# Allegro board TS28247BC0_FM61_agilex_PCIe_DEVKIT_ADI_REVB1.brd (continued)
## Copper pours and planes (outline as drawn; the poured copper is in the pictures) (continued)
SI5341_1P8V_VDDO on BOTTOM: 53.6,21.41 52.97,21.41 52.84,21.54 52.84,22.68 54.36,22.68 54.74,22.3 54.74,20.78 54.62,20.65 53.86,20.65 53.73,20.78 53.73,21.29
SI5341_1P8V_VDDO on L12_SIG4: 54.74,30.69 54.36,31.07 48.27,31.07 47.89,30.69 47.89,20.53 48.27,20.14 54.36,20.14 54.74,20.53
SI5341_2P5V_VDDO on BOTTOM: 47,21.29 47,22.56 47.12,22.68 48.01,22.68 48.14,22.56 48.14,21.41 48.01,21.29
SI5341_2P5V_VDDO on L03_SIG1: 52.84,24.34 51.44,22.94 51.44,22.05 51.19,21.8 46.62,21.8 46.24,22.18 46.24,26.24 46.62,26.62 52.46,26.62 52.84,26.24
SI5341_VDD on BOTTOM: 47.51,29.29 47.63,29.42 47.63,31.45 47.51,31.57 46.11,31.57 45.98,31.45 45.98,29.29
SI5341_VDD on L03_SIG1: 49.54,31.83 50.43,30.94 54.49,30.94 55.13,30.3 55.13,22.3 54.62,21.8 52.08,21.8 51.82,22.05 51.82,22.68 53.22,24.08 53.22,26.49 52.71,27 46.62,27 46.24,27.38 46.24,31.45 46.62,31.83
SI5341_VDDA on BOTTOM: 44.58,22.81 44.58,24.34 43.57,24.34 43.31,24.08 43.31,23.07 43.57,22.81
SW_U76_FPGA_VCC on TOP: 184.74,87.25 184.74,84.3 184.64,84.2 183.12,84.2 182.81,83.89 182.81,82.88 183.14,82.55 184.67,82.55 184.74,82.47 184.74,79.55 184.31,79.12 178.09,79.12 177.46,79.75 177.46,87.14 178,87.68 184.31,87.68
SW_U77_FPGA_VCC on TOP: 184.74,74.6 184.74,71.66 184.64,71.55 183.12,71.55 182.81,71.25 182.81,70.23 183.14,69.9 184.67,69.9 184.74,69.83 184.74,67.08 184.13,66.47 178.14,66.47 177.48,67.13 177.48,72.91 178.33,73.76 179.51,73.76 180.78,75.03 184.31,75.03
SW_U77_FPGA_VCC on BOTTOM, L07_SIG3, L16_SIG6: 184.74,74.6 184.74,67.08 184.13,66.47 181.06,66.47 179.13,68.4 179.13,73.38 180.78,75.03 184.31,75.03
SW_U78_FPGA_VCC on TOP: 184.74,59.06 184.74,56.11 184.72,56.09 183.19,56.09 182.81,55.7 182.81,54.69 183.14,54.36 184.67,54.36 184.74,54.28 184.74,51.36 184.31,50.93 178.29,50.93 177.49,51.73 177.49,58.61 178.37,59.49 184.31,59.49
SW_U78_FPGA_VCC on BOTTOM, L16_SIG6: 184.74,59.06 184.74,51.36 184.31,50.93 181.06,50.93 179.13,52.86 179.13,57.48 181.13,59.49 184.31,59.49
SW_U78_FPGA_VCC on L07_SIG3: 184.74,59.06 184.74,56.67 183.67,55.6 183.67,54.61 184.74,53.55 184.74,51.36 184.31,50.93 181.06,50.93 179.13,52.86 179.13,57.48 181.13,59.49 184.31,59.49
SW_U79_FPGA_VCC on TOP: 184.74,42.88 184.74,39.93 184.64,39.83 183.12,39.83 182.81,39.53 182.81,38.51 183.14,38.18 184.67,38.18 184.74,38.1 184.74,35.18 184.31,34.75 177.91,34.75 177.49,35.17 177.49,43.02 177.78,43.31 184.31,43.31
SW_U79_FPGA_VCC on BOTTOM, L16_SIG6: 184.74,42.88 184.74,35.18 184.31,34.75 181.06,34.75 179.13,36.68 179.13,41.3 181.13,43.31 184.31,43.31
UART_USB_PGND on BOTTOM: 19.59,106.35 19.59,107.04 20.58,108.03 20.58,108.79 15.25,108.79 15.25,108.03 16.26,107.01 16.26,106.38 15.37,105.49 15.37,104.98 15.25,104.85 13.85,104.85 13.85,106.89 13.34,107.39 13.34,110.44 22.49,110.44 22.49,107.9 20.66,106.07 19.87,106.07
UBII_M10_VCCA on BOTTOM: 25.28,28.15 24.01,28.15 23.76,27.89 23.76,26.11 24.01,25.86 25.28,25.86 25.53,26.11 25.53,27.89
UBII_M10_VCCA on L09_PWR1: 39.89,14.18 39.89,31.57 22.11,31.57 22.11,14.18
USB_UART_5V on L07_SIG3: 14.74,74.25 14.74,98.76 26.17,98.76 26.17,109.81 1.28,109.81 1.28,68.4 1.91,67.77 26.93,67.77 27.31,68.15 27.31,73.87 26.93,74.25
N17328275 on BOTTOM: 64.27,92.03 64.52,91.77 66.56,91.77 66.81,92.03 66.81,96.73 66.56,96.98 64.52,96.98 64.27,96.73
N31257069 on TOP: 54.36,5.79 53.98,6.17 53.98,8.46 54.24,8.71 54.87,8.71 55.13,8.46 55.13,5.92 55,5.79 55,3.38 54.87,3.25 54.49,3.25 54.36,3.38
N31257069 on BOTTOM: 54.24,7.19 54.87,7.19 55.13,7.44 55.13,10.75 55,10.87 54.49,10.87 54.49,9.6 53.98,9.1 53.98,7.44
N31416063 on BOTTOM: 244.36,83.37 244.61,83.11 246.34,83.11 246.36,83.14 246.36,85.04 246.29,85.12 244.58,85.12 244.36,84.89
N34525726 on TOP (solid shape): 268.87,110.13 272.25,108.91 273.3,105.48 273.3,17.17 273.1,15.32 272.09,13.75 143.17,13.75 143.17,14.43 167.7,14.43 167.7,15.83 169.23,17.36 170.77,15.83 170.77,14.43 190.56,14.43 190.56,15.8 192.08,17.34 193.63,15.83 193.63,14.43 211.51,14.43 211.51,15.75 213.05,17.29 214.59,15.75 214.59,14.43 246.44,14.43 246.44,15.75 247.99,17.28 249.49,15.7 249.49,14.43 265.38,14.43 265.67,14.59 265.69,14.93 266.97,19.91 272.1,19.55 272.42,19.5 272.6,19.78 272.6,102.68 272.34,103.08 271.86,103.02 266.53,103.28 266.18,108.61 266.22,109.15 265.77,109.43 249.51,109.43 249.51,108.08 247.97,106.54 246.44,108.08 246.44,109.43 215.5,109.43 215.5,108.11 213.98,106.54 212.43,108.08 212.43,109.43 194.9,109.43 194.9,108.11 193.36,106.57 191.83,108.11 191.83,109.43 130.13,109.43 130.13,108.11 128.61,106.54 127.06,108.08 127.06,109.43 101.18,109.43 101.18,108.11 99.65,106.54 98.1,108.08 98.1,109.43 72.35,109.43 72.35,108.11 70.82,106.54 69.27,108.08 69.27,109.43 37.88,109.43 37.88,108.11 36.35,106.54 34.81,108.08 34.81,109.43 24.14,109.43 24.14,110.13
N34525726 on BOTTOM (solid shape): 268.87,110.13 272.25,108.91 273.3,105.48 273.3,17.17 273.1,15.32 272.09,13.75 143.17,13.75 143.17,14.43 167.7,14.43 167.7,15.85 169.25,17.39 170.77,15.83 170.77,14.43 190.56,14.43 190.56,15.8 192.09,17.34 193.63,15.8 193.63,14.43 211.51,14.43 211.51,15.75 213.05,17.29 214.59,15.75 214.59,14.43 246.44,14.43 246.44,15.75 247.99,17.28 249.49,15.7 249.49,14.43 265.38,14.43 265.67,14.59 265.69,14.93 266.97,19.91 272.1,19.55 272.42,19.5 272.6,19.78 272.6,102.68 272.34,103.08 271.86,103.02 268.08,102.33 265.46,105.13 262.26,105.13 262.26,109.43 249.51,109.43 249.51,108.08 247.97,106.54 246.44,108.08 246.44,109.43 246.39,109.43 215.5,109.43 215.5,108.11 213.96,106.57 212.43,108.11 212.43,109.43 194.9,109.43 194.9,108.11 193.36,106.57 191.83,108.11 191.83,109.43 130.13,109.43 130.13,108.11 128.59,106.57 127.06,108.11 127.06,109.43 101.18,109.43 101.18,108.11 99.65,106.54 98.1,108.08 98.1,109.43 72.35,109.43 72.35,108.11 70.82,106.54 69.27,108.08 69.27,109.43 37.88,109.43 37.88,108.11 36.35,106.54 34.81,108.08 34.81,109.43 24.14,109.43 24.14,110.13
N34824147 on TOP (solid shape): 1.12,14.43 14.39,14.43 18.66,14.43 18.85,14.55 18.82,14.77 19.99,17.29 21.2,14.79 21.18,14.55 21.38,14.43 33.99,14.43 39.55,14.43 39.55,15.8 41.09,17.34 42.63,15.8 42.63,14.43 44.97,14.43 44.97,13.75 11.44,13.75 11.44,10.33 7.5,5.29 3.56,10.33 3.56,13.75 0.64,13.75 0.64,17.73 1.12,17.73
N34824147 on BOTTOM (solid shape): 1.12,14.43 14.39,14.43 18.47,14.43 18.47,15.8 20.01,17.34 21.55,15.8 21.55,14.43 33.99,14.43 39.55,14.43 39.55,15.8 41.09,17.34 42.63,15.8 42.63,14.43 44.97,14.43 44.97,13.75 11.44,13.75 11.44,10.33 7.5,5.29 3.56,10.33 3.56,13.75 0.64,13.75 0.64,17.73 1.12,17.73
N35351327 on TOP: 192.54,32.59 193.81,32.59 194.06,32.34 194.06,31.07 193.81,30.81 192.54,30.81
N35351327 on BOTTOM: 192.29,31.19 192.29,27 192.54,26.75 194.44,26.75 194.83,27.13 194.83,31.19 194.57,31.45 192.54,31.45
N35410578 on TOP: 192.54,24.97 193.56,24.97 193.81,24.72 193.81,23.45 193.56,23.19 192.54,23.19
N35410578 on BOTTOM: 192.92,19.26 194.57,19.26 194.83,19.51 194.83,23.45 194.57,23.7 192.67,23.7 192.67,19.51
N35982389 on BOTTOM: 37.98,102.69 46.98,102.69 47,102.57 47,103.71 45.22,103.71 45.22,105.62 44.08,105.62 44.08,103.71 37.98,103.71
N36079166 on BOTTOM: 40.27,46.81 40.39,46.69 40.39,45.93 40.14,45.67 38.11,45.67 37.85,45.42 37.85,43.51 36.08,43.51 36.08,46.56 36.33,46.81
N36194618 on BOTTOM: 128.15,50.5 128.15,49.35 127.52,48.72 126.37,48.72 125.61,49.48 125.61,51.26 125.99,51.64 125.99,51.89 125.7,52.18 125.7,53 125.97,53.27 126.37,53.04 126.37,52.83 126.26,52.64 126.27,52.47 126.91,52.42 127.64,51.68 127.64,50.75 127.9,50.75
N38179462 on BOTTOM: 217.43,19 217.43,17.99 217.69,17.73 219.34,17.73 219.59,17.99 219.59,18.75 219.34,19
N38179462 on L12_SIG4: 219.34,17.6 212.35,17.6 211.72,18.24 211.72,23.32 215.27,26.88 218.96,26.88 220.1,25.73 220.1,18.37
N40878945 on BOTTOM: 229.32,55.3 229.67,54.94 230.79,54.94 231.12,55.27 231.12,55.7 231.02,55.81 229.42,55.81 229.32,55.7
N40879092 on BOTTOM: 230.54,52.25 230.54,52.86 230.49,52.91 230.03,52.91 229.72,52.61 229.72,52.2 229.39,51.87 229.39,50.47 229.7,50.17 229.8,50.17 230.05,50.42 230.05,50.75 229.93,50.88 229.93,51.64 229.98,51.69 229.98,51.84 230.26,52.12 230.41,52.12
N40879329 on L16_SIG6: 230.59,52.1 230.59,50.42 230.74,50.27 231.2,50.27 231.22,50.29 231.22,52.07 231.1,52.2 230.69,52.2
N40879333 on L16_SIG6: 231.88,52.2 231.88,50.29 231.96,50.22 232.44,50.22 232.44,52.2 232.34,52.3 231.99,52.3
N42308549 on TOP: 230.41,27.41 230.41,28.04 229.85,28.6 229.85,30.15 230.26,30.56 233.43,30.56 233.76,30.23 233.76,28.35 233.33,27.92 233.33,27.33 233.26,27.26 230.56,27.26
N42744699 on BOTTOM: 66.43,104.6 64.52,104.6 64.27,104.35 64.27,99.65 64.52,99.39 66.43,99.39 66.68,99.65 66.68,104.35
N42745155 on BOTTOM: 96.4,100.66 96.4,104.35 98.81,104.35 99.07,104.09 99.07,100.92 98.81,100.66

Small or netless copper shapes (teardrops, artwork), in the pictures only: 65 on TOP, 3 on BOTTOM

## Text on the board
BOTTOM: 100-0330692-B1 | BOTTOM SIDE LAYER 18
Ref Des/Silkscreen Bottom: A | X1 | X4 | X8 | X16 | 1 | MSEL0 | 0 | MSEL1 | MSEL2 | Config Mode | AS_FAST | AS_NORMAL | C | SW1 | OPEN = Enable | Closed = Disable | CLOSE --> SELECT | OPEN --> DESELECT | JTAG MASTER
User.Comments: CR_111111_33 | CR_111111_31 | CR_111111_29 | CR_111111_28 | CR_UNNAMED_68 | CR_111111_30 | CR_111111_22 | CR_1_6 | CR_123_1 | CR_111111_18 | CR_111111_19 | CR_UNNAMED_45 | CR_111111_24 | CR_111111_17 | CR_111111_25 | CR_111111_23 | CR_111111_27 | CR_111111_21 | CR_111111_26 | CR_111111_20 | CR_UNNAMED_27 | CR_U34_2 | CR_UNNAMED_48 | CR_UNNAMED_38 | CR_111111_1 | CR_UNNAMED_31 | CR_UNNAMED_32 | CR_UNNAMED_28 | CR_UNNAMED_36 | CR_111111_2 | CR_111111_3 | CR_111111_4 | CR_U32_2 | CR_U32_1 | CR_4444_1 | CR_11_2 | CR_UNNAMED_56 | CR_UNNAMED_49 | CR_UNNAMED_23 | CR_Q4_3 | CR_U69_1 | CR_U17_1 | CR_654321_5 | CR_Q4_2 | CR_UNNAMED_30 | CR_UNNAMED_26 | CR_654321_4 | CR_123456_19 | CR_123456_52 | CR_123456_54 | CR_123456_8 | CR_1123_2 | CR_123456_56 | CR_123456_17 | CR_1111111_2 | CR_1111111_4 | CR_1111111_5 | CR_1111111_7 | CR_Q4_5 | CR_1111111_6 | CR_UNNAMED_74 | CR_1111111_9 | CR_1111111_10 | CR_1111111_1 | CR_123456_39 | CR_UNNAMED_53 | CR_UNNAMED_63 | CR_111111_32 | CR_41_2 | CR_41_3 | CR_123456_40 | CR_111111_59 | CR_111111_58 | CR_111111_55 | CR_111111_56 | CR_111111_57 | CR_111111_54 | CR_1111_2 | CR_111111_10 | CR_111111_11 | CR_111111_9 | CR_111111_12 | CR_111111_5 | CR_UNNAMED_77 | CR_UNNAMED_78 | CR_UNNAMED_79 | CR_111111_6 | CR_111111_8 | CR_111111_7 | CR_111111_35 | CR_111111_36 | CR_444444_2 | CR_UNNAMED_69 | CR_Q4_4 | CR_Q4_6 | MEZZANINE MODULE | NOTES: UNLESS OTHERWISE SPECIFIED | 1.  ASSEMBLY BOARD PER IPC-A-610 (LATEST REVISION) STANDARD. | 2.  HANDLE MOISTURE SENSITIVE DEVICES(MSD) PER MANUFACTURE'S | CALL OUT ON MSD LABEL.  IF MSD LABEL IS MISSING OR NOT LEGIBLE | 3.  USE IPC-7711/7721 (LATEST REVISION) FOR ALL PCBA REWORK. | THEN ALL PLASTIC PACKAGED COMPONENTS ARE TO BE CONSIDERED MSD | LEVEL 6 AND USE EIA/JEP 113-A FOR HANDLING.
TOP: TOP SIDE LAYER 1
Ref Des/Silkscreen Top: Z | R | TX | RX | B | D21 | G | QSFPDD0 | A | D22 | Y | D23 | QSFPDD1 | D24 | 0P9V_VCCRT_GXER1 | 1P2V_VCCR | Agilex  F-Series FPGA | TM | HPS DIMM | C | D | E | CH0 | CH1 | CH2 | CH3 | 12V_G1 | PVCC | 1P2V_DDR4_CH01 | VCCA_PLL | 2P5V | SDA | SCL | EN | 0P9V_VCCH | 12V_G2 | PG | GND | 3P3V | EXTERNAL JTAG | ADI DONGLE | HSSI_PWM | 1P8V | D14:FM6_CVP_CONFDONE | D13:FM6_CONF_DONE | CLKIN | CLKOUT | 5V | 12V_AUX | 12.5A | 3 | 2 | 1 | 0 | UART | IO_1P8V | 0P9V_VCCL_HPS | ALERTn | 1P2V_CH23 | IIN-_1 | Input | SEL_A_B# | CPU_RESETn | HPS_WARM_RESETn | HPS_COLD_RESETn | PCIE_EP_12V | PCIE_PERSTn | FX2_RESETn | FAN_CTRL | POWER_ON | OVERTEMPn | PWR_LED_DR | POWER INPUT
DIMENSION: R | 3X | 59.6 | 0.1339 | 0.0340 | 0.0551 | 0.0681 | 0.1585 | 0.2521 | 3.40 | 0.86 | 1.40 | 1.73 | 4.03 | 6.40 | 45 X.0200 | 45 X0.51 | 2X | 1.9 | .0748 | 2.74 | .1080 | 3.51 | .1380 | 266.8200 | 10.505
PAGE_OUTLINE: THIS DOCUMENT CONTAINS PROPRIETARY INFORMATION | OF INTEL CORP. NEITHER THE DOCUMENT NOR SAID | PROPRIETARY INFORMATION SHALL BE PUBLISHED, | REPRODUCED, COPIED, DISCLOSED OR USED FOR ANY | PURPOSE OTHER THAN CONSIDERATION OF THIS DOCUMENT | WITHOUT THE EXPRESS WRITTEN PERMISSION OF A DULY | AUTHORIZED REPRESENTATIVE OF INTEL CORPORATION | PROPRIETARY NOTICE: | R | REV | B1
User.20: 0.063 | 0.055
User.22: Place 0201, 0402 | No component | SECTION A-A | A
User.35: INTERNAL SIGNAL LAYER 3
User.36: INTERNAL GND PLANE LAYER 2
User.38: PRIMARY SIDE PASTE MASK
User.39: SECONDARY SIDE PASTE MASK
User.40: PRIMARY SIDE SILKSCREEN
User.41: SECONDARY SIDE SILKSCREEN
User.42: PRIMARY SIDE SOLDERMASK
User.43: SECONDARY SIDE SOLDERMASK
User.44: INTERNAL PWR PLANE LAYER 10
User.45: R | Max component height bottom side | of PCIe card: .105/2.67mm | DWG NO. | SIZE | SCALE: 1/1 | REV | CAGE CODE | SHEET 2 OF 2 | PROPRIETARY NOTICE: | THIS DOCUMENT CONTAINS PROPRIETARY INFORMATION | OF ALTERA CORP. NEITHER THE DOCUMENT NOR SAID | PROPRIETARY INFORMATION SHALL BE PUBLISHED, | REPRODUCED, COPIED, DISCLOSED OR USED FOR ANY | PURPOSE OTHER THAN CONSIDERATION OF THIS DOCUMENT | WITHOUT THE EXPRESS WRITTEN PERMISSION OF A DULY | AUTHORIZED REPRESENTATIVE OF ALTERA CORPORATION | DEC .XXXX  .002 | B1 | INTEL CONFIDENTIAL | 3065 BOWERS AVE | SANTA CLARA | CALIF.  95051 | NOTES:(UNLESS OTHERWISE SPECIFIED) | (USE FOR OSP ONLY ) | 19. VIA PLUGGING REQUIREMENTS FOR TEST PAD VIA (EXCEPTION IS NOTE 23): | THE VIAS THAT ARE USED AS TEST PADS ARE REQUIRED TO BE PLUGGED ON THE SIDE THAT | IS OPPOSITE TO THE TEST PADS. THE PLUGGED MATERIAL HAS TO BE FILLED AT LEAST 40% | AND NO MORE THAN 90% OF THE VIA HEIGHT MEASURED FROM THE SIDE OPPOSITE TO THE TEST | PADS. IT IS REQUIRED THAT AIR SHALL NOT FLOW THROUGH FROM ONE END OF THE TEST PAD | VIA TO THE OTHER. THERE IS NO CONTINUOUS AIR GAP FROM ONE END TO THE OTHER END | OF THE VIA. THEY ARE REQUIRED TO BE STUFFED 3 TIMES AS FOLLOWS: | a. STUFF SOLDERMASK INTO THE VIAS FROM THE SIDE OPPOSITE THE TEST PADS. | b. SEAL THE VIAS USING SOLDERMASK ON THE SIDE OPPOSITE OF THE TEST PADS. | c. SEAL THE VIAS USING SOLDERMASK ON THE TEST PAD SIDE. | d. MAKE SURE THE SOLDERMASK IS TOTALLY CLEANED FROM ALL TEST PADS DURING | THE SOLDERMASK CLEANING PROCESS. | (IMPEDANCES SUBJECT TO CHANGE PER PROJECT REQUIREMENTS) | 20. REQUIRED REPORT OF PRODUCTION BOARDS: | EVERY 3 OR LESS LOTS AND 5000 OR LESS BOARDS, THE FOLLOWING TESTS ARE REQUIRED | BEFORE THE BOARDS ARE SHIPPED OUT. A COPY OF THE REPORT AND IMPEDANCE COUPON | TO BE SENT TO THE ENGINEER INVOLVED. | a. MEASURE THE FOLLOWING IMPEDANCES OF 30 RANDOMLY PICKED BOARDS: | i. SEE IMEPACNE TABLE FOR REQUIRED IMPEDANCES AND LAYERS TO BE MEASURED. | b. MEASURE THE Tg OF A PIECE OF MATERIAL FROM THE BOARD PANEL. THE Tg VALUE | HAS TO BE GREATER THAN .145. | c. CROSS SECTION A TEST PAD VIA FROM EACH CORNER OF ONE PCB (4 TEST PADS VIAS TOTAL). | THEY HAVE TO BE PICKED FROM TEST PAD VIAS THAT ARE CLOSE TO EACH CORNER. | PICTURES OF THE CROSS SECTION SHOWING THE STUFFING ARE REQUIRED | IN THE REPORT. MEASURE THE PERCENTAGE OF THE STUFFING IN THE PLUGGED VIAS, | COPPER FOIL + PLATING THICKNESS (TOP TO BOTTOM), COPPER PLATING | THICKNESS IN HOLE (6 LOCATIONS - 2 TOPS, 2 MIDDLES AND 2 BOTTOMS), | DIELECTRIC THICKNESS (CENTER AND CORNER), | TRACE PROPERTY (TOP WIDTH, BANDWIDTH AND THICKNESS), AND BOARD THICKNESS (WITHOUT SOLDERMASK). | d. MEASURE ALSO THE FOLLOWING ITEMS FROM ONE BOARD: | i .   OSP THICKNESS | i i . BOW AND TWIST (MAX AND MIN ) | i i i PEEL STRENGTH | iv.   CLEANLINESS TEST | v.    SOLDERABILITY | v i . THERMAL STRESS | vii.  THE DIMENSIONS OF ONE OF EVERY KIND OF HOLE | viii. THE OUTER DIMENSIONS OF THE BOARD | 1. MATERIALS: MEG*6. | 2. THIS DRAWING ALSO EXISTS ON ELECTRONIC MEDIA. | 3. FABRICATE PWB PER IPC-6012 CLASS 2 (LATEST REVISION). | 4. DIMENSIONING AND TOLERANCING PER ANSI Y14.5M. | 5. BOARD MUST BE UL 94V-0 APPROVED. | 6. BREAKOUT IN THE REGION OF THE TRACE/PAD JUNCTION SHALL NOT REDUCE THE | TRACE WIDTH BY MORE THAN 25% UNLESS OTHERWISE SPECIFIED. | 7. COPPER IN HOLES SHALL BE PER IPC - 6012(LATEST REVISION), CLASS 2. | 8. MAXIMUM BOARD WARPAGE IN ANY DIRECTION TO BE ,0075'/INCH, AS MEASURED BY | IPC-TM-650 TEST METHOD 2.4.22. | 9. VENDOR MARKING: VENDOR LOGO, UL MARKING AND DATECODE (4DIGIT WWYY)TO BE IN | ETCH ON SECONDARY (BOTTOM) SIDE AWAY FROM ALL BOARD FEATURES. | 10. FEATURE SIZE TOLERANCE: PLATED THRU HOLE PADS, INTERNAL PLANE CLEARANCES | (ANTIPADS) AND SURFACE MOUNT LAND PATTERNS SHALL BE +/- 10% OF THEIR CAD | DIMENSION WITH THE FOLLOWING EXCEPTION. ANY SMT LAND PATTERNS THAT HAVE | A FINISHED PAD WIDTH OR DIAMETER LESS THAN OR EQUAL TO .012' MUST USE THE | FOLLOWING TOLERANCE, +/-.001'. PCB VENDOR TO ADJUST ARTWORK TO | COMPENSATE FOR ETCH PROCESS. NOTE: THIS APPLIES TO ETCH SIZES BEFORE SOLDERMASK. | FURTHERMORE, FOR ETCH COMPENSATION, ONLY MINIMAL AMOUNT IS ALLOWED. | NO GEOMETRIES MAY BE ENLARGED FOR YIELD PURPOSES. | FINISHED PRODUCT MUST MATCH INTEL CAD DATA AS CLOSE AS POSSIBLE. | 11. FEATURE LOCATION TOLERANCE: ALL CONDUCTIVE FEATURES SHALL BE WITHIN | .008' DIAMETER TRUE POSITION REGARDLESS OF FEATURE SIZE (RFS). | 12. HOLE LOCATION TOLERANCE: PLATED THRU HOLES SHALL BE WITHIN .003' DIAMETER | TRUE POSITION AT MAXIMUM MATERIAL CONDITION (MMC ) . NON-PLATED HOLES <.200" | SHALL BE WITHIN .003' DIAMETER TRUE POSITION WITH RESPECT TO 0,0 DATUM. | NON-PLATED HOLES >.200 SHALL BE WITHIN .003' DIAMETER TRUE POSITION WITH | RESPECT TO DATUM. | 13. SILKSCREEN BOTH SIDES USING NON - CONDUCTIVE INK. COLOR: WHITE. | NO SILKSCREEN SHALL BE ON ANY EXPOSED COPPER PAD. TRIMMING ALLOWED EVEN | IF IMPACT TO LEGIBILITY. | 14. REMOVE ALL UNUSED PADS FROM INNER LAYERS. | 15. IMPEDANCE TO BE VERIFIED PER TABLE. IMPEDANCE COUPONS MUST REFLECT EACH | CONTROLLED IMPEDANCE FOR EACH LAYER. MEASUREMENTS MUST BE PERFORMED BY TDR. | IMPEDANCE REPORTING MUST SPECIFY EACH CONTROLLED IMPEDANCE GEOMETRY BY LAYER. | FULL AND ACCURATE REPORTING AND COUPONS MUST BE PROVIDED WITH BOARDS. RECORDS | MUST BE MAINTAINED BY SUPPLIER FOR REFERENCE BY DESIGN TEAM AS REQUIRED. | REPORTS PER LOT INFORMATION PER DATE CODE MUST BE AVAILABLE UPON REQUEST. | 16. SURFACE FINISH: ENIG (ENTHONE HT PLUS,FORMOCHEM F35,SHIKOKU F2 (LX) PLUX | THICKNESS SHALL BE 0.25 TO 0.50 MICRON). | 17. VIAS THAT ARE MASKED OVER BY DESIGN ARE PLUGGED, 30% TO 90%. VIAS WITH | SOLDERMASK OPENINGS ON TOP SIDE ARE BY DESIGN AND REMAIN OPEN. | EXCEPTION IS NOTE 23 | 18. SOLDERMASK BOTH SIDES, USING GREEN MATTE OR GLOSS SOLDERMASK PER I PC-SM-840. | SOLDERMASK PADS SHALL BE ENLARGED BY .004" OVERALL OR .002' PER SIDE | INCLUDING SOLDERMASK DEFINED PADS. SOLDERMASK DEFINED PADS SHALL STRICTLY FOLLOW | .002' OVERSIZE PER SIDE. NOTE 22 IS THE EXCEPTION. | NO CHANGE ALLOWED WITHOUT INTEL APPROVAL. | 25. ADD COPPER THIEVING WHERE NECESSARY, AND MAINTAIN A CLEARANCES OF 35 MILS TO ALL NETS. | 21. EDGE CONNECTOR FINGERS:REQUIRE 30 MICRO INCHES HARD GOLD OVER 150-200 | MICRO INCHES OF NICKEL. | 22. FOR BGA "U2", ALL EXPOSED COPPER PADS, WHETHER SMD OR NSMD, MUST HAVE A 20 MILS PAD DIAMETER, | THEY ALL MUST BE EQUAL. | 23. FILL ALL 8MIL, 10MIL AND 12MIL DRILL HOLES USING NON - CONDUCTIVE EPOXY | 24. PLEASE ADD TEAR DROPS TO OUTER AND INNER LAYERS. | AND OVERPLATE WITH COPPER (VIPPO). | Layer | Impedance | 1 | 3 | 5 | 7 | 12 | 14 | 16 | 18 | 45 OHMS | (mils) | IMPEDANCE TABLE (SEE SPECIAL NOTE) | 5.85 | 3.2 | 3.5 | - MUST NOT CUT LAYER 16 | Width | 3.55/4.45 | 3.35/4.65 | 4.55/4.95 | 85 OHMS | / | SP | 4.00/5.00 | 3.10/5.90 | 3.35/5.65 | 90 OHMS | *** SPECIAL NOTES*** | 1. INNER LAYER IMPEDANCE IS +/-7% (BOTH FOR MASS AND SAMPLE PRODUCTION) | 2. OUYER LAYER IMPEDANCE IS +/-10% (BOTH FOR MASS AND SAMPLE PRODUCTION) | 3. THROUGH HOLE VIA 8MILS DRILL : FINISHED HOLE WITH EPOXY AND PLATED SHUT ALMOST 6MIL | 4. MICRO VIA 1-3 & 16-18 : 10 MIL DRILL; FILLED MICRO-VIA WITH EPOXY. | 3.2/9.6 | 100 OHMS | INTERNAL GND PLANE LAYER 11 | INTERNAL GND PLANE LAYER 13 | INTERNAL GND PLANE LAYER 15 | INTERNAL GND PLANE LAYER 17 | INTERNAL GND PLANE LAYER 4 | INTERNAL GND PLANE LAYER 6 | INTERNAL GND PLANE LAYER 8 | INTERNAL PWR PLANE LAYER 9 | INTERNAL SIGNAL LAYER 12 | INTERNAL SIGNAL LAYER 14 | INTERNAL SIGNAL LAYER 16 | INTERNAL SIGNAL LAYER 5 | INTERNAL SIGNAL LAYER 7 | INTERNAL XXX LAYER 18 | INTERNAL XXX LAYER 19 | INTERNAL XXX LAYER 20 | INTERNAL XXX LAYER 21 | INTERNAL XXX LAYER 22 | INTERNAL XXX LAYER 23 | INTERNAL XXX LAYER 24 | INTERNAL XXX LAYER 25 | INTERNAL XXX LAYER 26 | INTERNAL XXX LAYER 27 | INTERNAL XXX LAYER 28 | INTERNAL XXX LAYER 29 | INTERNAL XXX LAYER 30 | PRESS FIT | BACKDRILL DIAMETER | (D2=D1+8mils) | .050 CENTERS TYP. | THRU VIA 1-18 | MICRO VIA 16-18 | .100 TABS TYP. | MICRO VIA 1-2 | .025 NPTH TYP (3 PLCS) | .100 TYP. | L010/PLN - 1.0 Oz Cu | L011/PLN - 1.0 Oz Cu | L013/PLN - 0.5 Oz Cu | L014/SIG - 0.5 Oz Cu | L015/PLN - 0.5 Oz Cu | L016/SIG - 0.5 Oz Cu | L017/PLN - 0.5 Oz Cu | L018/BOT - 0.5 Oz Cu | L01/TOP - 0.5 Oz Cu 0.6 MILS THK | L012/SIG - 0.5 Oz Cu | L02/PLN - 0.5 Oz Cu | L03/SIG - 0.5 Oz Cu | L04/PLN - 0.5 Oz Cu | L05/SIG - 0.5 Oz Cu | L06/PLN - 0.5 Oz Cu | L07/SIG - 0.5 Oz Cu | L08/PLN - 1.0 Oz Cu | L09/PLN - 1.0 Oz Cu | MICRO VIA 1-3 | 1078 Core  - 3 MILS THK | 1035 Core  - 2 MILS THK | Pre-1035HRC -2.3 MILS THK | COPPER PLATE 1.4MILS THK | Pre-1035HRC -2.7 MILS THK | Pre-1078LRC -2.7 MILS THK | Pre-1027/1035HRC -3.8 MILS THK | CHAMFER EDGE CONNECTOR | 1.3 MILS THK | SCALE: NONE | 0.6 MILS THK | 0.6 MILS FOIL | 0.6MILS THK | 20.0 +/-2 | .045+/-.005 | 1.14+/-0.13 | FOIL | SEE STACKUP | LPHTE | HVLP | FIGURE | FINISHED_SIZE | 10.0 | DRILL CHART: L16_SIG6 to BOTTOM | ALL UNITS ARE IN MILS | DRILL CHART: TOP to L03_SIG1 | DRILL CHART: TOP to L02_GND1 | TOLERANCE_DRILL | +0.0/-10.0 | PLATED | DETAIL "A" | DETAIL "B" | QTY | 32 | 350 | 35 | TOOLING HOLE SIZE/LOCATION DETERMINED BY FAB VENDOR (4 PLCS) | 8.0 | 12.0 | 20.0 | 31.0 | 32.0 | 35.0 | 40.0 | 41.339 | 43.0 | 44.882 | 47.0 | 50.0 | 61.0 | 62.0 | 71.0 | 80.0 | 97.0 | 125.0 | 181.102 | 30.0 | 49.0 | 94.0 | 118.0 | 128.0 | 33.46x25.59 | 51.181x23.622 | 97.0x48.0 | DRILL CHART: TOP to BOTTOM | +0.0/-8.0 | +0.0/-12.0 | +3.0/-3.0 | +1.969/-1.969 | +5.0/-0.0 | +2.0/-2.0 | NON-PLATED | 8699 | 917 | 33 | 6 | 24 | 2 | 10 | 4 | 8 | 15 | Thickness After plating | (not including solder mask) | .0621  +/-.005 | + | - | 100-0330692-B1 | DETAIL | (CROSS SECTION) | AGILEX FPGA DEVKIT-ADI | SECONDARY SIDE SHOWN | BOTTOM SIDE SHOWN | TOP SIDE SHOWN | PRIMARY SIDE SHOWN | D | N/A | B | A
